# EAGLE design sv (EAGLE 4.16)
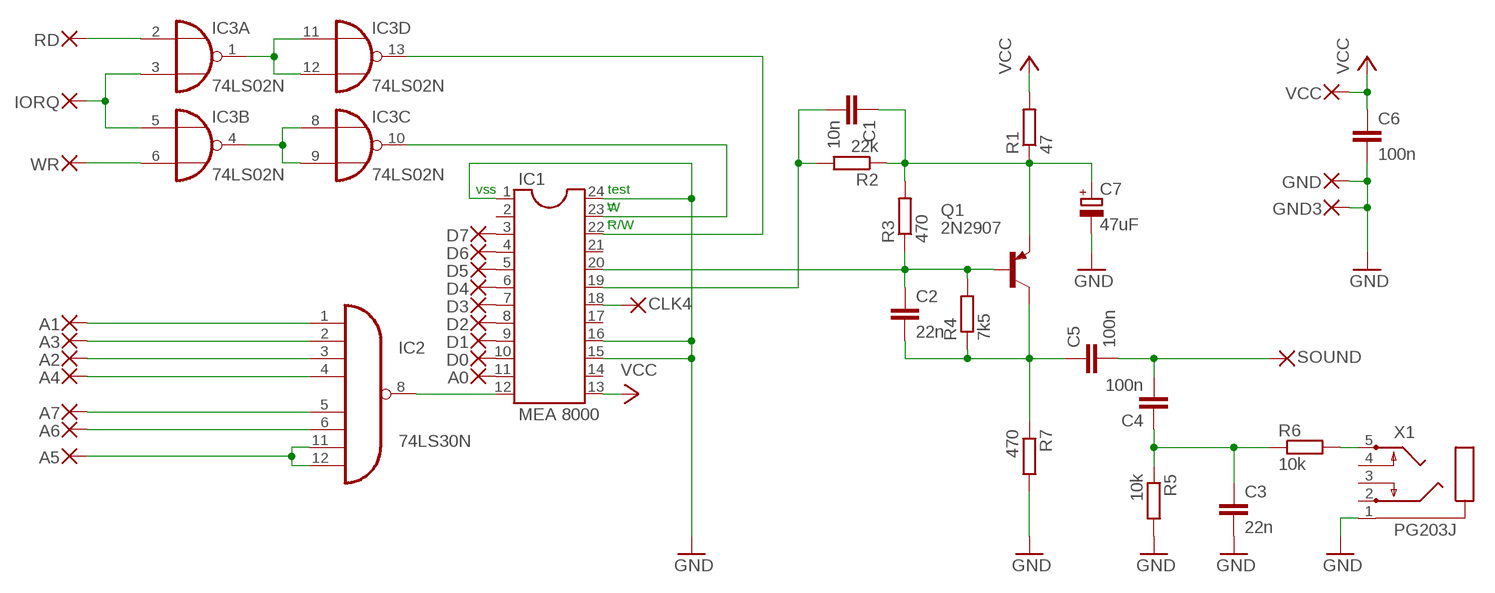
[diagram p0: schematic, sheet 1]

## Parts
A0  1,27-REDONDO1.0  [1,27/1,0-REDONDO]
A1  1,27-REDONDO1.0  [1,27/1,0-REDONDO]
A2  1,27-REDONDO1.0  [1,27/1,0-REDONDO]
A3  1,27-REDONDO1.0  [1,27/1,0-REDONDO]
A4  1,27-REDONDO1.0  [1,27/1,0-REDONDO]
A5  1,27-REDONDO1.0  [1,27/1,0-REDONDO]
A6  1,27-REDONDO1.0  [1,27/1,0-REDONDO]
A7  1,27-REDONDO1.0  [1,27/1,0-REDONDO]
C1  10n  C-EU050-024X044  [C050-024X044]
C2  22n  C-EU050-024X044  [C050-024X044]
C3  22n  C-EU050-024X044  [C050-024X044]
C4  100n  C-EU075-032X103  [C075-032X103]
C5  100n  C-EU075-032X103  [C075-032X103]
C6  100n  C-EU075-032X103  [C075-032X103]
C7  47uF  CPOL-EUE5-6  [E5-6]
CLK4  1,27-REDONDO1.0  [1,27/1,0-REDONDO]
D0  1,27-REDONDO1.0  [1,27/1,0-REDONDO]
D1  1,27-REDONDO1.0  [1,27/1,0-REDONDO]
D2  1,27-REDONDO1.0  [1,27/1,0-REDONDO]
D3  1,27-REDONDO1.0  [1,27/1,0-REDONDO]
D4  1,27-REDONDO1.0  [1,27/1,0-REDONDO]
D5  1,27-REDONDO1.0  [1,27/1,0-REDONDO]
D6  1,27-REDONDO1.0  [1,27/1,0-REDONDO]
D7  1,27-REDONDO1.0  [1,27/1,0-REDONDO]
GND  1,27-REDONDO1.0  [1,27/1,0-REDONDO]
GND3  1,27-REDONDO1.0  [1,27/1,0-REDONDO]
IC1  MEA 8000  DIL24-6  [DIL24-6]
IC2  74LS30N  [DIL14]
IC3  74LS02N  [DIL14]
IORQ  1,27-REDONDO1.0  [1,27/1,0-REDONDO]
Q1  2N2907  [TO18]
R1  47  R-EU_0207/10  [0207/10]
R2  22k  R-EU_0207/10  [0207/10]
R3  470  R-EU_0207/10  [0207/10]
R4  7k5  R-EU_0207/10  [0207/10]
R5  10k  R-EU_0207/10  [0207/10]
R6  10k  R-EU_0207/10  [0207/10]
R7  470  R-EU_0207/10  [0207/10]
RD  1,27-REDONDO1.0  [1,27/1,0-REDONDO]
SOUND  1,27-REDONDO1.0  [1,27/1,0-REDONDO]
VCC  1,27-REDONDO1.0  [1,27/1,0-REDONDO]
WR  1,27-REDONDO1.0  [1,27/1,0-REDONDO]
X1  PG203J  [PG203J]

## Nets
GND: C3.2 C6.2 C7.- GND3.P$1(P) GND.P$1(P) IC1.1 IC1.15 IC1.16 IC1.24 R5.2 R7.2 X1.1
N$1: D0.P$1(P) IC1.10
N$2: D1.P$1(P) IC1.9
N$3: D2.P$1(P) IC1.8
N$4: D3.P$1(P) IC1.7
N$5: D4.P$1(P) IC1.6
N$6: D5.P$1(P) IC1.5
N$7: D6.P$1(P) IC1.4
N$8: D7.P$1(P) IC1.3
N$9: IC1.12 IC2.8(O)
N$10: IC1.23 IC3.10(C:O)
N$11: IC3.4(B:O) IC3.8(C:I0) IC3.9(C:I1)
N$12: IC3.2(A:I0) RD.P$1(P)
N$13: IC3.3(A:I1) IC3.5(B:I0) IORQ.P$1(P)
N$14: IC3.6(B:I1) WR.P$1(P)
N$15: IC3.1(A:O) IC3.11(D:I0) IC3.12(D:I1)
N$16: IC1.22 IC3.13(D:O)
N$17: A1.P$1(P) IC2.1(I0)
N$18: A3.P$1(P) IC2.2(I1)
N$19: A2.P$1(P) IC2.3(I2)
N$20: A4.P$1(P) IC2.4(I3)
N$21: A7.P$1(P) IC2.5(I4)
N$22: A6.P$1(P) IC2.6(I5)
N$23: A5.P$1(P) IC2.11(I6) IC2.12(I7)
N$24: A0.P$1(P) IC1.11
N$26: R6.2 X1.5
N$40: C1.2 IC1.19 R2.2
N$45: C1.1 C7.+ Q1.1(E) R1.1 R2.1 R3.2
N$51: C2.1 IC1.20 Q1.2(B) R3.1 R4.2
N$53: C2.2 C5.1 Q1.3(C) R4.1 R7.1
N$54: C4.2 C5.2 SOUND.P$1(P)
N$55: C3.1 C4.1 R5.1 R6.1
N$56: CLK4.P$1(P) IC1.18
VCC: C6.1 IC1.13 R1.2 VCC.P$1(P)
Unconnected: IC1.2 IC1.14 IC1.17 IC1.21 X1.2 X1.3 X1.4

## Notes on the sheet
- vss
- test
- _
- _
- W
- _
- R/W

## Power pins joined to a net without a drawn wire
GND: IC2.7(GND) IC3.7(P:GND)
VCC: IC2.14(VCC) IC3.14(P:VCC)

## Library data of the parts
A0 A1-A7 CLK4 D0 D1-D7 GND GND3 IORQ RD SOUND VCC WR = wirepad2:1,27-REDONDO
C1-C6 = rcl:C-EU: CAPACITOR, European symbol
C7 = rcl:CPOL-EU: POLARIZED CAPACITOR, European symbol
IC1 = ic-package:DIL24: Dual In Line
IC2 = 74xx-eu:74*30: 8-input NAND gate
IC3 = 74xx-eu:74*02: Quad 2-input NOR gate
Q1 = transistor-pnp:2N2907*: PNP Transistor
R1-R7 = rcl:R-EU_: RESISTOR, European symbol
X1 = con-hirschmann:PG203J: MIC/HEADPHONE JACK KS-S stereo microphone/headphone jack PG203JN (Schukat)

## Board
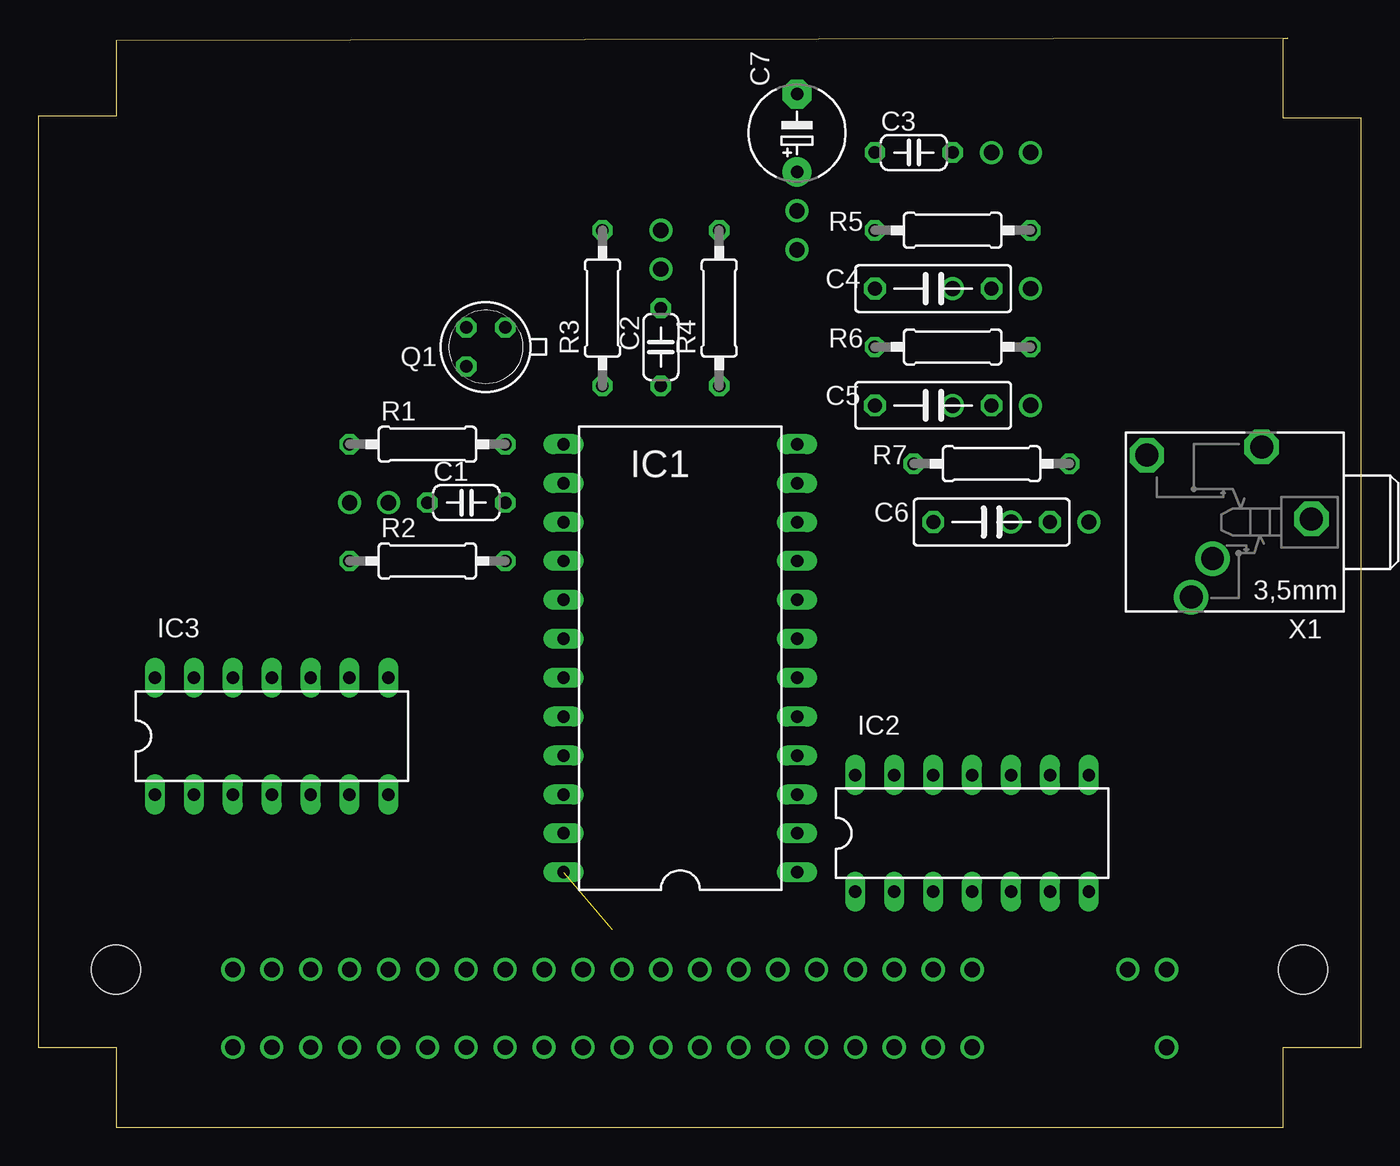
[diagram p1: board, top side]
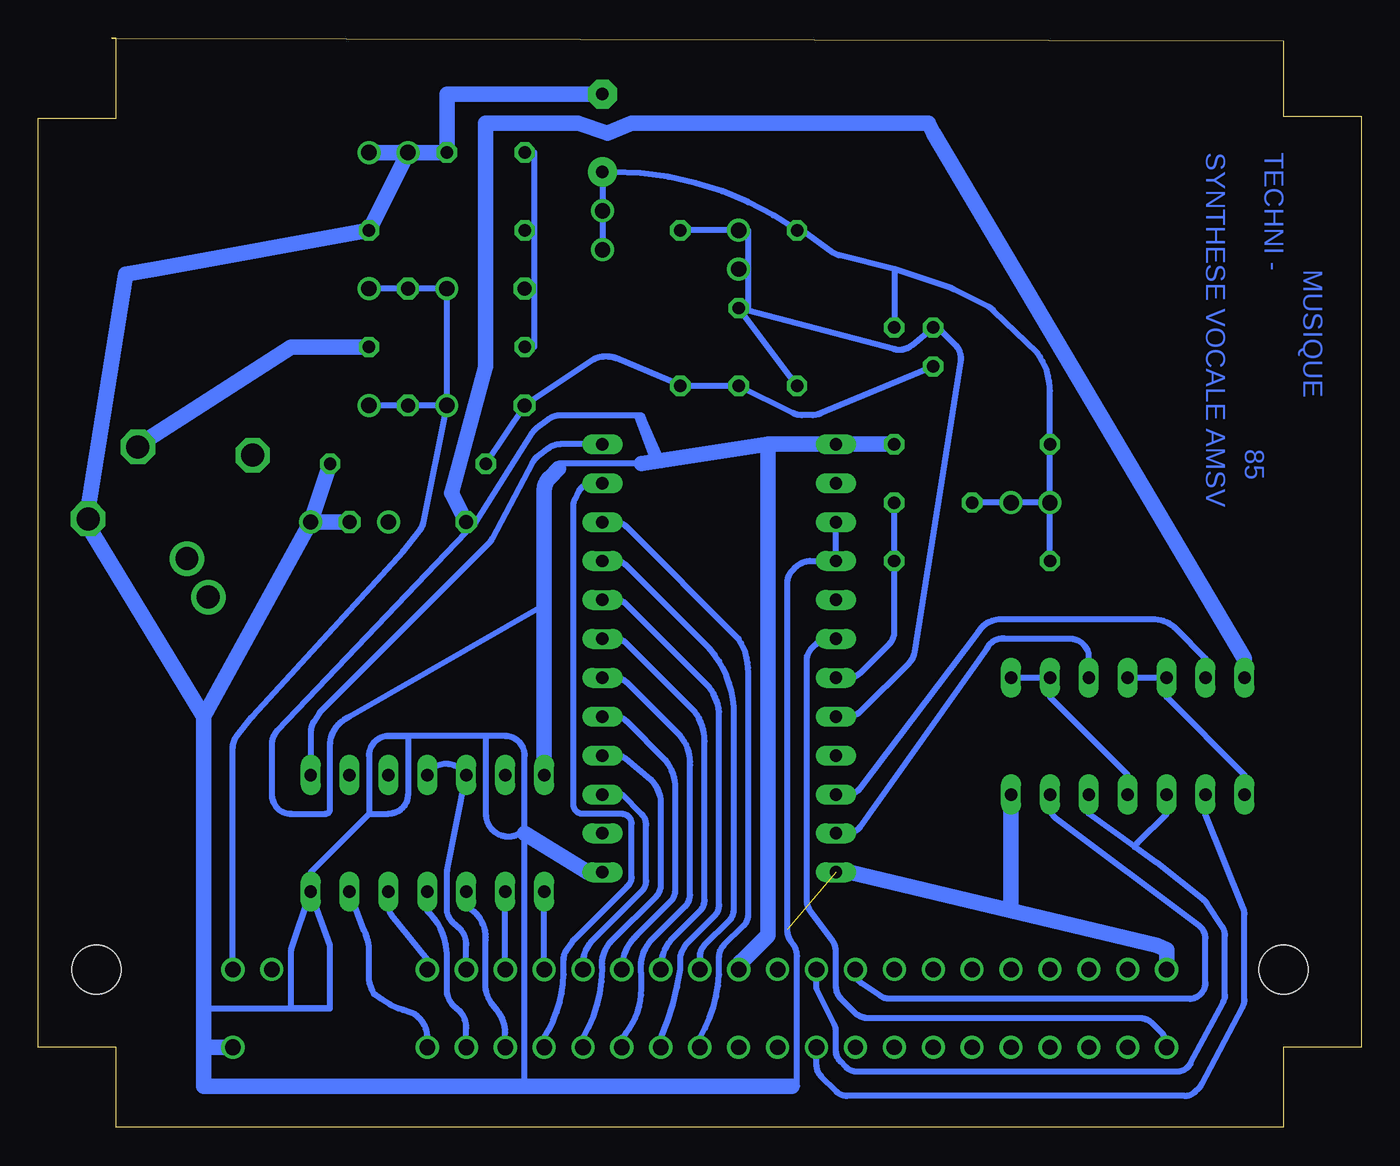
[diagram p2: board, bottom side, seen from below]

Size 86.36 x 71.11 mm. Coordinates in mm from the lower left corner, seen from the top.
Outline: 81.28,0 81.28,5.23 86.36,5.23 86.36,65.87 81.28,65.87 81.28,71.11 81.58,71.11 5.08,70.95 5.08,66.03 0.01,66.03 0,6.5 0,5.23 5.08,5.23 5.08,0 81.28,0
Copper layers (1*16): Top 0.035mm / dielectric 1.5mm / Bottom 0.035mm
Design rules "default": minimum track width 10mil, minimum drill 24mil, track to track 8mil, track to pad 8mil, pad to pad 8mil, via to via 8mil, smd to smd 8mil, copper to edge 40mil, drill to drill 8mil, minimum pad ring 10mil, minimum via ring 8mil, stop-mask expansion 4mil, vias tented up to drill 0mil, thermal gap 10mil
Holes 3.2 mm at 5.08,10.31 82.55,10.31

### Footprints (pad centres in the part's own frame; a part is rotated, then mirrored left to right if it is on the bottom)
1,27/1,0-REDONDO = drill 1.016 pad 1.422 round: P$1 0,0
C050-024X044 = drill 0.813 octagon: 1 -2.54,0; 2 2.54,0
C075-032X103 = drill 0.914 octagon: 1 -3.81,0; 2 3.81,0
E5-6 = drill 0.813 pad 1.905 round: + -2.54,0 | drill 0.813 pad 1.905 octagon: - 2.54,0
DIL24-6 = drill 0.813 long: 1 -13.97,-7.62; 2 -11.43,-7.62; 3 -8.89,-7.62; 4 -6.35,-7.62; 5 -3.81,-7.62; 6 -1.27,-7.62; 7 1.27,-7.62; 8 3.81,-7.62; 9 6.35,-7.62; 10 8.89,-7.62; 11 11.43,-7.62; 12 13.97,-7.62; 13 13.97,7.62; 14 11.43,7.62; 15 8.89,7.62; 16 6.35,7.62; 17 3.81,7.62; 18 1.27,7.62; 19 -1.27,7.62; 20 -3.81,7.62; 21 -6.35,7.62; 22 -8.89,7.62; 23 -11.43,7.62; 24 -13.97,7.62
DIL14 = drill 0.813 long: 1 -7.62,-3.81; 2 -5.08,-3.81; 3 -2.54,-3.81; 4 0,-3.81; 5 2.54,-3.81; 6 5.08,-3.81; 7 7.62,-3.81; 8 7.62,3.81; 9 5.08,3.81; 10 2.54,3.81; 11 0,3.81; 12 -2.54,3.81; 13 -5.08,3.81; 14 -7.62,3.81
TO18 = drill 0.813 octagon: 1 -1.27,-1.27; 2 1.27,-1.27; 3 1.27,1.27
0207/10 = drill 0.813 octagon: 1 -5.08,0; 2 5.08,0
PG203J = drill 1.499 octagon: 1 -5.004,-0.203; 4 5.74,-4.369; 5 -1.753,-4.902 | drill 1.499 round: 2 2.845,4.902; 3 1.448,2.388

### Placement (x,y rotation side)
A0  53.34,5.23 0 bottom
A1  53.34,10.31 0 bottom
A2  55.88,5.23 0 bottom
A3  55.88,10.31 0 bottom
A4  58.42,5.23 0 bottom
A5  58.42,10.31 0 bottom
A6  60.96,5.23 0 bottom
A7  60.96,10.31 0 bottom
C1  27.94,40.79 0 top
C2  40.64,50.95 270 top
C3  57.15,63.65 0 top
C4  58.42,54.76 0 top
C5  58.42,47.14 0 top
C6  62.23,39.52 0 top
C7  49.53,64.92 90 top
CLK4  12.7,5.23 0 bottom
D0  43.18,5.23 0 bottom
D1  43.18,10.31 0 bottom
D2  45.72,5.23 0 bottom
D3  45.72,10.31 0 bottom
D4  48.26,5.23 0 bottom
D5  48.26,10.31 0 bottom
D6  50.8,5.23 0 bottom
D7  50.8,10.31 0 bottom
GND  12.7,10.31 0 bottom
GND3  73.66,5.23 0 top
IC1  41.91,30.63 90 top
IC2  60.96,19.2 0 top
IC3  15.24,25.55 0 top
IORQ  35.56,10.31 0 top
Q1  29.21,50.95 180 top
R1  25.4,44.6 0 top
R2  25.4,36.98 0 top
R3  36.83,53.49 90 top
R4  44.45,53.49 90 top
R5  59.69,58.57 0 top
R6  59.69,50.95 0 top
R7  62.23,43.33 0 top
RD  35.56,5.23 0 top
SOUND  73.66,10.31 0 top
VCC  40.64,10.31 0 bottom
WR  33.02,10.31 0 top
X1  78.11,39.52 180 top

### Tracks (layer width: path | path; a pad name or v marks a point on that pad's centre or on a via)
GND  (via drill 1)  (1 unrouted)
  Bottom 0.406: IC2.7 67.31,11.9 67.31,7.77 | IC2.7 69.85,11.58 69.85,7.77 67.31,7.77 | 75.56,7.77 67.31,7.77 | IC2.7 68.58,16.66 64.77,20.47 | 64.77,20.47 64.77,24.28 arc90 63.5,25.55 | 64.77,20.47 63.5,20.47 arc-90 62.23,21.74 62.23,25.55 63.5,25.55 | 57.15,25.55 63.5,25.55 | 57.15,25.55 55.88,25.55 arc90 54.61,24.28 54.61,19.2 54.61,2.69 | 57.15,25.55 57.15,20.47 arc-121 54.93,19.2 | IC1.15 IC1.16 35.99,36.98 arc-45 36.88,36.61 37.09,36.4 arc-45 37.47,35.5 37.47,12.92 arc-34 37.25,12.22 37.04,11.9 arc34 36.83,11.2 36.83,2.69 37.15,2.69
  Bottom 1.016: 75.56,5.23 GND3.P$1 | 75.56,5.23 75.56,7.77 75.56,26.82 | 75.56,5.23 75.56,2.69 54.61,2.69 37.15,2.69 | IC1.1 50.48,16.66 54.61,19.2 | IC1.24 33.34,16.66 22.92,14.18 | 22.92,14.18 13.34,11.9 12.7,11.58 GND.P$1 | 22.92,14.18 22.86,14.44 IC3.7 | C7.- 59.69,67.46 C3.2 v62.23,63.65 | v62.23,63.65 R5.2 78.74,56.03 80.64,55.71 83.19,39.84 X1.1 83.19,39.52 82.87,38.89 75.56,26.82 | v62.23,63.65 v64.77,63.65 | v68.58,39.52 R7.2 | v68.58,39.52 C6.2 | 75.56,26.82 v68.58,39.52
N$1
  Bottom 0.406: IC1.10 48.67,39.52 arc45 47.97,39.23 40.64,31.9 arc33 40.01,29.68 40.01,13.9 arc45 40.3,13.19 41.62,11.88 arc-45 41.91,11.17 41.91,9.99 arc28 43.18,5.87 D0.P$1
N$2
  Bottom 0.406: IC1.9 48.67,36.98 arc45 47.97,36.69 42.55,31.27 arc37 40.96,27.46 40.96,14.22 arc45 41.25,13.51 42.89,11.88 arc-45 43.18,11.17 D1.P$1
N$3
  Bottom 0.406: IC1.8 48.67,34.44 arc45 47.97,34.15 42.55,28.73 arc30 41.91,27.14 41.91,14.54 arc45 42.2,13.83 44.02,12.01 arc-18 44.2,11.75 44.34,11.48 arc-27 44.45,11.03 44.45,10.31 arc16 45.72,5.87 D2.P$1
N$4
  Bottom 0.406: IC1.7 48.67,31.9 arc45 47.97,31.61 43.5,27.14 arc37 42.86,25.23 42.86,14.85 arc45 43.16,14.15 45.09,12.22 arc-43 D3.P$1
N$5
  Bottom 0.406: IC1.6 48.67,29.36 arc45 47.97,29.07 44.45,25.55 arc44 43.81,23.65 43.81,15.17 arc45 44.11,14.46 46.35,12.22 arc-51 46.99,9.99 46.99,9.04 arc44 48.26,5.87 D4.P$1
N$6
  Bottom 0.406: IC1.5 48.67,26.82 arc45 47.97,26.53 45.4,23.96 arc34 44.77,22.38 44.77,15.49 arc45 45.06,14.78 47.31,12.54 arc-49 D5.P$1
N$7
  Bottom 0.406: IC1.4 48.62,24.28 arc40 47.98,24.05 46.35,22.7 arc37 45.72,21.43 45.72,15.81 arc45 46.01,15.1 48.9,12.22 arc-54 49.53,10.31 arc29 50.8,5.87 D6.P$1
N$8
  Bottom 0.406: IC1.3 48.26,21.74 46.97,20.45 arc45 46.67,19.74 46.67,16.12 arc45 46.97,15.42 50.16,12.22 arc-56 D7.P$1
N$9
  Bottom 0.406: IC1.12 52.28,44.6 arc-37 53.04,44.35 53.75,43.82 arc-25 54.11,43.4 56.74,38.42 arc17 56.97,38.12 67.86,27.23 arc-11 68.02,27.04 68.37,26.51 arc-34 68.58,25.8 IC2.8
N$10
  Bottom 0.406: IC1.23 33.54,19.2 arc-55 32.72,19.62 24.45,31.27 arc74 23.18,31.9 19.05,31.9 arc74 17.78,30.95 IC3.10
N$11
  Bottom 0.406: IC3.8 IC3.9 20.32,28.09 15.24,23.01 IC3.4
N$12
  Bottom 0.406: IC3.2 10.16,20.47 7.69,14.3 arc22 7.62,13.93 7.62,8.34 arc28 7.74,7.87 10.41,2.83 arc17 10.58,2.59 10.82,2.35 arc45 11.53,2.06 33.56,2.06 arc45 34.27,2.35 35.27,3.35 arc45 35.56,4.06 RD.P$1
N$13
  Bottom 0.406: IC3.5 17.78,20.47 14.79,18.32 | 14.79,18.32 13.35,17.28 arc93 13.32,17.28 10.28,14.86 arc18 10.07,14.63 9.06,13.09 arc33 8.89,12.54 8.89,8.66 arc28 9.01,8.19 11.15,4.17 arc62 12.03,3.65 32.92,3.65 arc45 33.63,3.94 34,4.3 arc45 34.29,5.01 34.29,6.27 arc-27 34.4,6.71 35.56,9.04 IORQ.P$1 | IC3.3 12.7,20.47 14.61,18.57 14.79,18.32
N$14
  Bottom 0.406: IC3.6 20.32,20.97 arc-53 19.92,20.17 10.56,13.15 arc53 10.16,12.35 10.16,9.46 arc45 10.45,8.75 10.5,8.7 arc45 11.21,8.41 30.81,8.41 arc34 31.37,8.58 32.58,9.38 arc56 33.02,10.21 WR.P$1
N$15
  Bottom 0.406: IC3.11 IC3.12 12.7,28.09 7.62,23.01 IC3.1
N$16
  Bottom 0.406: IC1.22 33.52,21.74 arc-53 32.72,22.14 25.08,32.22 arc64 23.5,33.17 13.65,33.17 arc46 12.06,32.54 10.16,30.63 IC3.13
N$17
  Bottom 0.406: A1.P$1 IC2.1
N$18
  Bottom 0.406: A3.P$1 IC2.2
N$19
  Bottom 0.406: A2.P$1 55.88,6.18 arc-44 56.52,7.77 arc34 57.15,9.04 57.15,12.22 arc-67 58.42,14.44 IC2.3
N$20
  Bottom 0.406: A4.P$1 58.42,6.5 arc-53 59.05,7.77 arc53 59.69,9.04 59.69,11.27 arc-48 60.96,14.12 IC2.4
N$21
  Bottom 0.406: A7.P$1 60.96,10.95 63.28,13.85 arc39 63.5,14.47 IC2.5
N$22
  Bottom 0.406: A6.P$1 60.96,5.87 arc-62 61.91,7.46 arc-3 62.87,7.77 arc12 64.45,8.72 arc16 64.77,9.68 64.77,11.58 arc-28 65.09,12.85 IC2.6
N$23
  Bottom 0.406: A5.P$1 58.42,11.9 arc-53 59.05,13.17 arc44 59.69,14.12 59.69,16.56 arc11 59.67,16.76 IC2.12 58.74,23.33 arc-106 IC2.11
N$24
  Bottom 0.406: IC1.11 50.18,42.06 arc-63 51.08,41.51 51.33,41 arc-27 51.44,40.56 51.44,21.11 arc-90 50.8,20.47 48.26,20.47 arc90 47.62,19.84 47.62,16.34 arc53 47.94,15.71 51.37,12.29 arc-11 51.49,12.14 51.9,11.52 arc-34 52.07,10.96 52.07,9.99 arc32 53.34,5.87 A0.P$1
N$25  (via drill 1)
  other vias: 71.12,10.31
N$26
  Bottom 1.016: R6.2 69.85,50.95 79.69,44.6 X1.5
N$27  (via drill 1)
  other vias: 38.1,10.31
N$28  (via drill 1)
  other vias: 22.86,5.23
N$29  (via drill 1)
  other vias: 20.32,10.31
N$30  (via drill 1)
  other vias: 30.48,10.31
N$31  (via drill 1)
  other vias: 27.94,10.31
N$32  (via drill 1)
  other vias: 25.4,10.31
N$33  (via drill 1)
  other vias: 22.86,10.31
N$34  (via drill 1)
  other vias: 63.5,39.52
N$35  (via drill 1)
  other vias: 17.78,10.31
N$36  (via drill 1)
  other vias: 15.24,10.31
N$37  (via drill 1)
  other vias: 15.24,5.23
N$38  (via drill 1)
  other vias: 17.78,5.23
N$39  (via drill 1)
  other vias: 20.32,5.23
N$40
  Bottom 0.406: C1.2 R2.2 30.48,32.32 arc45 30.77,31.61 32.73,29.66 arc45 33.43,29.36 IC1.19
N$41  (via drill 1)
  other vias: 25.4,5.23
N$42  (via drill 1)
  other vias: 27.94,5.23
N$43  (via drill 1)
  other vias: 30.48,5.23
N$44  (via drill 1)
  other vias: 33.02,5.23
N$45  (via drill 1)
  Bottom 0.406: v20.32,40.79 v22.86,40.79 C1.1 | R2.1 v20.32,40.79 | v20.32,40.79 R1.1 20.32,48.08 arc-37 21.16,50.58 23.99,53.3 arc-27 24.34,53.6 26.61,54.73 arc-8 26.74,54.79 30.48,56.03 | v49.53,57.3 v49.53,59.84 C7.+ 48.9,62.38 arc35 R3.2 arc-70 36.51,58.57 34.44,57.1 arc-22 34.11,56.94 30.48,56.03 | 30.48,56.03 Q1.1
N$46  (via drill 1)
  other vias: 38.1,5.23
N$47  (via drill 1)
  other vias: 40.64,5.23
N$51  (via drill 1)
  Bottom 0.406: IC1.20 33.55,26.82 arc-45 32.65,27.19 29.5,30.34 arc-36 29.14,31.04 26.14,50 arc-54 26.49,51.09 27.4,52 arc-45 Q1.2 29.34,51.05 arc55 30.48,50.8 C2.1 | C2.1 R3.1 | C2.1 40.01,53.49 40.01,56.03 | 40.01,56.03 v40.64,56.03 | 40.01,56.03 40.01,58.57 v40.64,58.57 R4.2
N$53
  Bottom 0.406: Q1.3 35.33,46.61 arc23 35.81,46.51 36.53,46.51 arc27 37.1,46.64 C2.2 R4.1 45.09,48.73 48.66,50.22 arc-23 49.15,50.32 49.46,50.32 arc-34 50.17,50.1 C5.1 R7.1
N$54  (via drill 1)
  Bottom 0.406: v59.69,47.14 v59.69,54.76 C4.2 v64.77,54.76 | v59.69,47.14 C5.2 v64.77,47.14 | v59.69,47.14 61.22,39.51 arc27 61.47,38.96 62.55,37.62 72.36,26.85 arc-4 72.42,26.79 73.38,25.58 arc-39 73.66,24.79 SOUND.P$1
N$55
  Bottom 0.406: C3.1 53.98,63.65 53.98,58.57 | 53.98,58.57 R5.1 | 53.98,54.76 53.98,58.57 | 53.98,54.76 C4.1 | 53.98,54.76 53.98,50.95 R6.1
N$56
  Bottom 0.406: CLK4.P$1 12.7,5.34 arc-45 13.07,6.24 13.6,6.77 arc-45 14.5,7.14 32.18,7.14 arc45 33.08,7.51 33.92,8.35 arc45 34.29,9.25 34.29,11.48 arc-37 34.54,12.24 35.94,14.1 arc37 36.2,14.86 36.2,30.58 arc45 35.61,31.53 arc45 34.72,31.9 IC1.18
VCC
  Bottom 0.406: 46.99,43.33 52.39,43.33 52.39,43.01 | 57.78,39.52 54.1,45.36 arc21 53.79,45.7 53.04,46.25 arc37 52.28,46.51 47.31,46.51 | 47.31,46.51 46.99,46.51 | 45.7,43.53 45.72,43.65 46.99,46.51 | 46.99,46.51 46.04,43.97 46.35,43.97 47.31,46.51 | C6.1 57.78,39.52 | 57.78,39.52 70.77,25.89 arc-44 71.12,25.01 71.12,21.74 arc-90 69.85,20.47 67.63,20.47 arc-90 67.31,20.79 67.31,24.92 arc67 66.04,26.82 53.34,34.12
  Bottom 1.016: VCC.P$1 40.64,10.63 arc45 40.42,10.85 38.73,12.54 38.73,44.6 | 38.73,44.6 IC1.13 R1.2 | IC2.14 53.34,34.12 53.34,41.54 arc45 52.97,42.43 52.39,43.01 | 38.73,44.6 45.7,43.53 46.99,43.33 | IC3.14 7.62,30.63 27.94,64.92 28.26,65.56 47.62,65.56 49.21,64.92 51.12,65.56 57.15,65.56 57.15,49.68 59.37,41.43 C6.1

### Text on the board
Bottom: TECHNI - | SYNTHESE VOCALE AMSV | MUSIQUE | 85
